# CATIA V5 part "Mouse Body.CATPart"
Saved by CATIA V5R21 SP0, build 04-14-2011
Part number: Mouse Body
Bounding box of the stored display mesh (mm): x -45 to 70, y -41 to 41, z -20 to 35
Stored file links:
  C:\CATIA V5_2015\ASD\Mouse Assembly Template\Mouse Body.CATPart
  C:\CATIA V5_2015\ASD\Mouse Assembly Template\Mouse Assembly Template.CATProduct
  C:\CATIA V5_2015\ASD\Mouse Assembly Template\Skeleton.CATPart
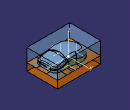
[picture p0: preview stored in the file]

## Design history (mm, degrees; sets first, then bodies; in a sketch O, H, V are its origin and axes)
Parameters
  ZMax = 10 mm
  ZMin = 20 mm
  XMax = 10 mm
  XMin = 10 mm
  YMax = 10 mm
  YMin = 10 mm
  DraftAngle = 0 deg
  Tesselation1 = 0.01 mm
  Tesselation2 = -1 mm
  `Compute Mode` = 0
  ValExplode = 10 mm
  Stroke = 0 mm
  `Stroke Angle` = 0 deg
External parameters (linked from other documents)
  `External.Mouse Front Radius Value` = 4 mm
  `External.Mouse Rear Radius Value` = 15 mm
AxisSystem1 "Main Pulling Direction.1": origin (0, 0, 0), X (1, 0, 0), Y (0, 1, 0), Z (0, 0, 1)
Set1
  Sketch1 "Mouse Main Sketch", origin (0, 0, 0), H (1, 0, 0), V (0, 1, 0), geometry linked from another document
  DatumSurface1 "Top Surface": linked copy from another document
  Sketch2 "Mouse Button Sketch02", origin (0, 0, 0), H (1, 0, 0), V (0, 0, 1), geometry linked from another document
  Sketch3 "Mouse Button Sketch01", origin (0, 0, 0), H (1, 0, 0), V (0, 1, 0), geometry linked from another document
  Plane1: linked copy from another document
Set2 "Mouse Body Surface"
  Set3 "Cavity Body"
    Set4 "Operation Body"
      Sweep1: type Segment, GuideCrv Sketch1, Length1 40, Length2 0, Angle 3, DraftDirection xy-plane
      Trim1: Trimmed (Sweep1; DatumSurface1)
      Fillet1: on edge [face of DatumSurface1 | face of Sweep1]
      Offset1: Offset Fillet1, Length 1.2
      Extrude1: Element1 Sketch2, Lim1 45, Lim2 45
      Sweep2: type Segment, GuideCrv Sketch3, Length1 40, Length2 0, Angle 3, DraftDirection xy-plane
      Trim2: Trimmed (Extrude1; Sweep2)
      Trim3: Trimmed (Trim2; Offset1)
    Trim4 "Final Cavity Surface": Trimmed (Fillet1; Trim3)
  Set5 "Core Body"
    Set6 "Operation Body"
      Offset2: Offset Fillet1, Length 1.5
      Offset3: Offset Offset1, Length 1.2
      Offset4: Offset Trim2, Length -1.2
      Trim5: Trimmed (Offset4; Offset3)
      Trim6: Trimmed (Trim5; Offset2)
      Offset5: Offset Fillet1, Length 1
      Sweep3 "Parting Surface": type Segment, GuideCrv {intersect ToIntersect1 xy-plane, ToIntersect2 Offset5}, Length1 2, Length2 10, Angle 90, DraftDirection xy-plane
      Offset6: Offset Sweep3, Length -1.5
      Trim7: Trimmed (Sweep3; Offset5)
      Trim8: Trimmed (Trim7; Offset6)
    Trim9 "Final Core Surface": Trimmed (Trim8; Trim6)
  Trim10 "Final Mouse Body": Trimmed (Trim4; Trim9)
  Point1: (0, 0, 0)
Set7 "Bounding Box Elements.1"
  Extremum1: Reference Assemble1, Direction edge [XY plane of AxisSystem1 | ZX plane of AxisSystem1], Direction2 edge [YZ plane of AxisSystem1 | XY plane of AxisSystem1], Direction3 edge [ZX plane of AxisSystem1 | YZ plane of AxisSystem1]
  Extremum2: Reference Assemble1, Direction edge [XY plane of AxisSystem1 | ZX plane of AxisSystem1], Direction2 edge [YZ plane of AxisSystem1 | XY plane of AxisSystem1], Direction3 edge [ZX plane of AxisSystem1 | YZ plane of AxisSystem1]
  Extremum3: Reference Assemble1, Direction edge [YZ plane of AxisSystem1 | XY plane of AxisSystem1], Direction2 edge [ZX plane of AxisSystem1 | YZ plane of AxisSystem1], Direction3 edge [XY plane of AxisSystem1 | ZX plane of AxisSystem1]
  Extremum4: Reference Assemble1, Direction edge [YZ plane of AxisSystem1 | XY plane of AxisSystem1], Direction2 edge [ZX plane of AxisSystem1 | YZ plane of AxisSystem1], Direction3 edge [XY plane of AxisSystem1 | ZX plane of AxisSystem1]
  Extremum5: Reference Assemble1, Direction edge [ZX plane of AxisSystem1 | YZ plane of AxisSystem1], Direction2 edge [XY plane of AxisSystem1 | ZX plane of AxisSystem1], Direction3 edge [YZ plane of AxisSystem1 | XY plane of AxisSystem1]
  Extremum6: Reference Assemble1, Direction edge [ZX plane of AxisSystem1 | YZ plane of AxisSystem1], Direction2 edge [XY plane of AxisSystem1 | ZX plane of AxisSystem1], Direction3 edge [YZ plane of AxisSystem1 | XY plane of AxisSystem1]
  Plane2: type OffsetPt, RefPlane XY plane of AxisSystem1, RefPoint Extremum5
  Plane3: type OffsetPt, RefPlane XY plane of AxisSystem1, RefPoint Extremum6
  Plane4: type OffsetPt, RefPlane YZ plane of AxisSystem1, RefPoint Extremum1
  Plane5: type OffsetPt, RefPlane YZ plane of AxisSystem1, RefPoint Extremum2
  Plane6: type OffsetPt, RefPlane ZX plane of AxisSystem1, RefPoint Extremum3
  Plane7: type OffsetPt, RefPlane ZX plane of AxisSystem1, RefPoint Extremum4
  Plane8: type Offset, RefPlane Plane2, ZMax 10
  Plane9: type Offset, RefPlane Plane3, ZMin 20, reversed
  Plane10: type Offset, RefPlane Plane4, XMax 10
  Plane11: type Offset, RefPlane Plane5, XMin 10, reversed
  Plane12: type Offset, RefPlane Plane6, YMax 10
  Plane13: type Offset, RefPlane Plane7, YMin 10, reversed
  Intersect1: ToIntersect1 Plane8, ToIntersect2 Plane10
  Intersect2: ToIntersect1 Plane8, ToIntersect2 Plane11
  Intersect3: ToIntersect1 Plane8, ToIntersect2 Plane12
  Intersect4: ToIntersect1 Plane8, ToIntersect2 Plane13
  Intersect5: ToIntersect1 Intersect1, ToIntersect2 Intersect3
  Intersect6: ToIntersect1 Intersect3, ToIntersect2 Intersect2
  Intersect7: ToIntersect1 Intersect2, ToIntersect2 Intersect4
  Intersect8: ToIntersect1 Intersect1, ToIntersect2 Intersect4
  Line1: type PtPt, FirstPoint Intersect5, SecondPoint Intersect6
  Line2: type PtPt, FirstPoint Intersect6, SecondPoint Intersect7
  Line3: type PtPt, FirstPoint Intersect7, SecondPoint Intersect8
  Line4: type PtPt, FirstPoint Intersect8, SecondPoint Intersect5
  Join1: Elements (Line1; Line2; Line3; Line4)
Set8
  DatumSurface2 "Cavity Surface"
  DatumSurface3 "Core Surface"
  Sweep4 "Parting Surface": type Segment, GuideCrv {boundary Boundary edge of DatumSurface3}, Length1 50, Length2 0, Angle 90, DraftDirection Plane1
  Join2 "Final Cavity Surface": Elements (DatumSurface2; Sweep4)
  Join3 "Final Core Surface": Elements (Sweep4; DatumSurface3)
Body1 (main body)
  Body2
    CloseSurface1: CloseElement Trim10
  Assemble1: tool Body2
Body3 "Cavity Body"
  Pad1: profile Join1, up to Plane9
  Split1: SplitPlane Join2
Body4 "Core Body"
  Pad2: profile Join1, up to Plane9
  Split2: SplitPlane Join3
Relations
  `Fillet1.nls://PartDesignNLS/Radius` = `External.Mouse Front Radius Value`
  `Fillet1.nls://PartDesignNLS/Radius` = `External.Mouse Rear Radius Value`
